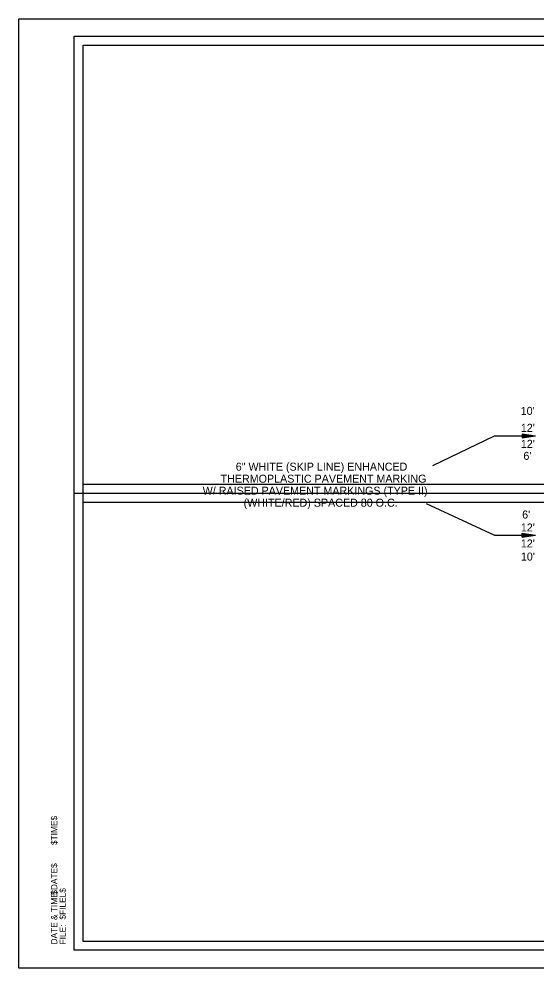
# Model space of a CAD drawing. Extents: x 1369895 to 1370228, y 380116 to 380329.
# Drawn here: x 1369894.7 to 1370011, y 380115.9 to 380329.2 of the extents above; entities that cross this region are included whole.
import ezdxf

# ---------------------------------------------------------------- set-up
doc = ezdxf.new("R2010")
doc.units = 0
for name, color, linetype in [('Default', 7, 'Continuous'), ('R_Border', 7, 'Continuous'), ('R_Border Notes', 7, 'Continuous'), ('R_Border Plan-Plan', 7, 'Continuous'), ('R_No Plot', 7, 'Continuous'), ('R_Proposed Road', 7, 'Continuous')]:
    doc.layers.add(name, color=color, linetype=linetype)

msp = doc.modelspace()

# ---------------------------------------------------------------- linework, layer by layer
at = {"layer": 'Default'}
for p, q in [((1370007.81, 380236), (1370010.81, 380235.55)), ((1370007.81, 380236), (1370007.81, 380235.1)), ((1370007.81, 380236), (1370010.81, 380235.55)), ((1370007.81, 380236), (1370007.81, 380235.1)), ((1370007.81, 380236), (1370010.81, 380235.55)), ((1370007.81, 380236), (1370007.81, 380235.1)), ((1370007.81, 380235.92), (1370010.31, 380235.55)), ((1370007.81, 380235.92), (1370010.31, 380235.55)), ((1370007.81, 380235.92), (1370010.31, 380235.55)), ((1370007.81, 380235.85), (1370009.79, 380235.55)), ((1370007.81, 380235.85), (1370009.79, 380235.55)), ((1370007.81, 380235.85), (1370009.79, 380235.55)), ((1370007.81, 380235.77), (1370009.29, 380235.55)), ((1370007.81, 380235.77), (1370009.29, 380235.55)), ((1370007.81, 380235.77), (1370009.29, 380235.55)), ((1370007.81, 380235.7), (1370008.78, 380235.55)), ((1370007.81, 380235.7), (1370008.78, 380235.55)), ((1370007.81, 380235.7), (1370008.78, 380235.55)), ((1370007.81, 380235.62), (1370008.28, 380235.55)), ((1370007.81, 380235.62), (1370008.28, 380235.55)), ((1370007.81, 380235.62), (1370008.28, 380235.55)), ((1370007.81, 380235.1), (1370010.81, 380235.55)), ((1370007.81, 380235.4), (1370008.78, 380235.55)), ((1370007.81, 380235.25), (1370009.79, 380235.55)), ((1370007.81, 380235.18), (1370010.31, 380235.55)), ((1370007.81, 380235.33), (1370009.29, 380235.55)), ((1370007.81, 380235.48), (1370008.28, 380235.55)), ((1370007.81, 380235.1), (1370010.81, 380235.55)), ((1370007.81, 380235.4), (1370008.78, 380235.55)), ((1370007.81, 380235.25), (1370009.79, 380235.55)), ((1370007.81, 380235.18), (1370010.31, 380235.55)), ((1370007.81, 380235.33), (1370009.29, 380235.55)), ((1370007.81, 380235.48), (1370008.28, 380235.55)), ((1370007.81, 380235.1), (1370010.81, 380235.55)), ((1370007.81, 380235.4), (1370008.78, 380235.55)), ((1370007.81, 380235.25), (1370009.79, 380235.55)), ((1370007.81, 380235.18), (1370010.31, 380235.55)), ((1370007.81, 380235.33), (1370009.29, 380235.55)), ((1370007.81, 380235.48), (1370008.28, 380235.55)), ((1370007.81, 380213.64), (1370010.81, 380213.19)), ((1370007.81, 380212.74), (1370007.81, 380213.64)), ((1370007.81, 380213.64), (1370010.81, 380213.19)), ((1370007.81, 380212.74), (1370007.81, 380213.64)), ((1370007.81, 380213.64), (1370010.81, 380213.19)), ((1370007.81, 380212.74), (1370007.81, 380213.64)), ((1370007.81, 380213.56), (1370010.31, 380213.19)), ((1370007.81, 380213.56), (1370010.31, 380213.19)), ((1370007.81, 380213.56), (1370010.31, 380213.19)), ((1370007.81, 380213.49), (1370009.79, 380213.19)), ((1370007.81, 380213.49), (1370009.79, 380213.19)), ((1370007.81, 380213.49), (1370009.79, 380213.19)), ((1370007.81, 380213.41), (1370009.29, 380213.19)), ((1370007.81, 380213.41), (1370009.29, 380213.19)), ((1370007.81, 380213.41), (1370009.29, 380213.19)), ((1370007.81, 380213.34), (1370008.78, 380213.19)), ((1370007.81, 380213.34), (1370008.78, 380213.19)), ((1370007.81, 380213.34), (1370008.78, 380213.19)), ((1370007.81, 380213.26), (1370008.28, 380213.19)), ((1370007.81, 380213.26), (1370008.28, 380213.19)), ((1370007.81, 380213.26), (1370008.28, 380213.19)), ((1370007.81, 380212.74), (1370010.81, 380213.19)), ((1370007.81, 380213.04), (1370008.78, 380213.19)), ((1370007.81, 380212.89), (1370009.79, 380213.19)), ((1370007.81, 380212.82), (1370010.31, 380213.19)), ((1370007.81, 380212.97), (1370009.29, 380213.19)), ((1370007.81, 380213.12), (1370008.28, 380213.19)), ((1370007.81, 380212.74), (1370010.81, 380213.19)), ((1370007.81, 380213.04), (1370008.78, 380213.19)), ((1370007.81, 380212.89), (1370009.79, 380213.19)), ((1370007.81, 380212.82), (1370010.31, 380213.19)), ((1370007.81, 380212.97), (1370009.29, 380213.19)), ((1370007.81, 380213.12), (1370008.28, 380213.19)), ((1370007.81, 380212.74), (1370010.81, 380213.19)), ((1370007.81, 380213.04), (1370008.78, 380213.19)), ((1370007.81, 380212.89), (1370009.79, 380213.19)), ((1370007.81, 380212.82), (1370010.31, 380213.19)), ((1370007.81, 380212.97), (1370009.29, 380213.19)), ((1370007.81, 380213.12), (1370008.28, 380213.19))]:
    msp.add_line(p, q, dxfattribs=at)
at = {"layer": 'R_Border'}
for p, q in [((1369907.12, 380325.35), (1370223.3, 380325.35)), ((1369907.12, 380119.89), (1369907.12, 380325.35)), ((1369907.12, 380119.89), (1369907.12, 380119.89)), ((1370223.3, 380119.89), (1369907.12, 380119.89))]:
    msp.add_line(p, q, dxfattribs=at)
at = {"layer": 'R_Border Plan-Plan'}
msp.add_line((1369907.12, 380222.62), (1370223.3, 380222.62), dxfattribs=at)
at = {"layer": 'R_No Plot'}
for points in [[(1369894.71, 380329.25), (1370228.05, 380329.25), (1370228.05, 380115.91), (1369894.71, 380115.91)], [(1370221.3, 380224.62), (1369909.12, 380224.62), (1369909.12, 380323.35), (1370158.66, 380323.35), (1370158.66, 380313.47), (1370176.2, 380313.47), (1370200.3, 380313.47), (1370200.3, 380291.14), (1370221.3, 380291.14)], [(1369909.12, 380323.35), (1370158.66, 380323.35), (1370158.66, 380313.47), (1370176.2, 380313.47), (1370200.3, 380313.47), (1370200.3, 380291.14), (1370221.3, 380291.14), (1370221.3, 380121.89), (1369909.12, 380121.89)], [(1369909.12, 380220.62), (1370221.3, 380220.62), (1370221.3, 380121.89), (1369909.12, 380121.89)]]:
    msp.add_lwpolyline(points, close=True, dxfattribs=at)
at = {"layer": 'R_Proposed Road'}
for p, q in [((1370001.59, 380235.55), (1370010.81, 380235.55)), ((1370001.59, 380235.55), (1370010.81, 380235.55)), ((1370001.59, 380213.19), (1370010.81, 380213.19)), ((1370001.59, 380213.19), (1370010.81, 380213.19))]:
    msp.add_line(p, q, dxfattribs=at)
for points in [[(1369987.77, 380228.85), (1370001.59, 380235.55), (1370010.81, 380235.55)], [(1369986.28, 380220.32), (1370001.59, 380213.19), (1370010.81, 380213.19)]]:
    msp.add_lwpolyline(points, dxfattribs=at)

# ---------------------------------------------------------------- texts
at = {"layer": 'Default'}
for s, p in [("10'", (1370007.51, 380240.25)), ("12'", (1370007.54, 380236.44)), ("12'", (1370007.54, 380232.84)), ("6'", (1370008.12, 380230.14)), ("6'", (1370007.84, 380216.94)), ("12'", (1370007.54, 380214.04)), ("12'", (1370007.54, 380210.44)), ("10'", (1370007.55, 380207.5))]:
    msp.add_text(s, height=1.8, rotation=360, dxfattribs=at).set_placement(p)
for s, p in [('6" WHITE (SKIP LINE) ENHANCED ', (1369943.45, 380227.71)), ('THERMOPLASTIC PAVEMENT MARKING', (1369940.04, 380225.01)), ('W/ RAISED PAVEMENT MARKINGS (TYPE II)', (1369936.01, 380222.31)), ('(WHITE/RED) SPACED 80 O.C.', (1369945.22, 380219.61))]:
    msp.add_text(s, height=1.8, dxfattribs=at).set_placement(p)
at = {"layer": 'R_Border Notes'}
for s, height, p in [('$TIME$', 1.397, (1369903.32, 380143.56)), ('$DATE$', 1.397, (1369903.32, 380132.39)), ('$FILEL$', 1.397, (1369905.24, 380126.8)), ('DATE & TIME:', 1.3968, (1369903.32, 380121.21)), ('FILE: ', 1.397, (1369905.24, 380121.21))]:
    msp.add_text(s, height=height, rotation=90, dxfattribs=at).set_placement(p)

doc.saveas('drawing.dxf')
